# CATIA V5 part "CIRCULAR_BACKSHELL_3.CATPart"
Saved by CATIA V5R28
Part number: CIRCULAR_BACKSHELL_3
Revision: --A
Publications: "Logical Termination.1", "BCP", "BCPRPoint_generated(BCP)", "BCPPlane_generated(BCP)", "BaCP", "Face_generated(BaCP)", "Face_generated(BaCP).1", "MasterKeywayAxis", "Axis_generated(BaCP)"
Bounding box of the stored display mesh (mm): x 0 to 66.176, y -13.041 to 13.041, z -13.893 to 13.843
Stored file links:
  C:\Users\ajc8720\Documents\BOEING_WORK\0001-2CES\004-AP242\Boeing-Generic_Harness_R3\CIRCULAR_BACKSHELL_3.CATPart
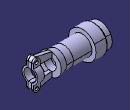
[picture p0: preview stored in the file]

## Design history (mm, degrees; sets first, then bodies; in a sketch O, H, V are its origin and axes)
Parameters
  PartNumber = "CIRCULAR_BACKSHELL_3"
AxisSystem1 "MasterKeywayAxis": origin (0, 0, 0), X (1, 0, 0), Y (0, 1, 0), Z (0, 0, 1)
Set1
  Point1: (34.417 {= Sketch2.distance(P3 V)}, 12.7, 0)
  Plane1: type 1Line1Pt, RefPoint Point1, Line Sketch2.L1
  Point2: type OnCurve, Support Sketch2.L4, Ratio 0.5
  Line1: type PtDir, RefPoint Point2, Direction (0, 1, 0), Start 0, End 5.08
  Point3: type OnCurve, Support Line1, Ratio 0.5
  Plane2: type 1Line1Pt, RefPoint Point3, Line Sketch2.L4
  Point4: type Center, Curve edge [face of Shaft1 from Sketch1.L5 | face of Shaft1 from Sketch1.L6]
  Plane3: type Tangent, Support face of Shaft1 from Sketch1.L5, RefPoint Point4
  Plane4: type OffsetPt, RefPlane Plane2, RefPoint Sketch2.P10
  Line2: type PtPt, FirstPoint vertex [face of Pad3 from Sketch5.L6 | face of Pad3 from Sketch5.L12 | end face of Pad3], SecondPoint vertex [face of Pad3 from Sketch5.L3 | face of Pad3 from Sketch5.L4 | start face of Pad3]
  Point5: type OnCurve, Support Line2, Ratio 0.5
  Plane5: type Tangent, Support face of Pad3 from Sketch5.L6, RefPoint Point5
Set2 "EGF"
  Set3 "BCP"
    Point6 "BCPRPoint": type Center, Curve edge [start face of Pad4 | face of Pad4 from Sketch6.A3]
    Plane6 "BCPPlane": type Tangent, Support start face of Pad4, RefPoint Point6
  Set4 "BaCP"
    Point7 "BaCPRPoint": type Center, Curve edge [face of Shaft1 from Sketch1.L6 | face of Shaft1 from Sketch1.L7]
    Plane7 "BaCPCPlane": type Tangent, Support face of Shaft1 from Sketch1.L7, RefPoint Point7
    Line3 "BaCPCLine": type PtDir, RefPoint Point7, Direction (0, 1, 0), Start 0, End 5.08
Body1 (main body)
  Sketch1 on xy-plane, origin (0, 0, 0), H (1, 0, 0), V (0, 1, 0)
    line L1 (0, 8.7249) -> (0, 11.43)
    line L2 (0, 11.43) -> (4.7625, 11.43)
    point P3 (4.7625, 11.43)
    line L3 (4.7625, 11.43) -> (6.3754, 13.0429)
    line L4 (6.3754, 13.0429) -> (16.764, 13.0429)
    line L5 (16.764, 13.0429) -> (16.764, 5.6896)
    line L6 (16.764, 5.6896) -> (7.747, 5.6896)
    line L7 (7.747, 5.6896) -> (7.747, 8.7249)
    line L8 (7.747, 8.7249) -> (0, 8.7249)
    axis line L9 (-2.2417, 0) -> (20.7737, 0)
    point P9 (-2.2417, 0)
    distance P3 L1 = 4.7625
    angle L3 L4 = 45
    distance L1 L7 = 7.747
    distance L1 L5 = 16.764
    distance L6 H = 5.6896
    distance L8 H = 8.7249
    distance L2 H = 11.43
    distance L4 H = 13.0429
    vertical: L1 V, L5 V, L7 V
    horizontal: L2 H, L4 H, L6 H, L8 H, L9 H
    coincidence: L1 V, P9 H
  Shaft1: profile Sketch1, axis Sketch1.L9, angle 360
  Sketch2 on zx-plane, origin (0, 0, 0), H (-1, 0, 0), V (0, 0, 1)
    line L1 (-34.417, 0) -> (-34.4298, 29.2976)
    line L2 (-34.417, 0) -> (-36.5055, 0)
    point P3 (-34.417, 0)
    line L3 (-34.417, 0) -> (-40.767, -0.0055)
    line L4 (-40.767, -0.0055) -> (-40.6296, -157.4316)
    reference projected point E1 (-34.417, 0) from Point1
    point P7 (-40.767, -0.0055)
    line L5 (-47.117, -0.0111) -> (-46.9796, -157.4371)
    construction line L6 (-40.767, -0.0055) -> (-47.117, -0.0111)
    construction line L7 (-40.6296, -157.4316) -> (-46.9796, -157.4371)
    point P10 (-47.117, -0.0111)
    point P11 (-34.417, 0)
    angle L1 V = 0.025
    distance P3 V = 34.417
    distance L4 E1 = 6.35
    angle L3 H = 0.05
    distance L4 L5 = 6.35
    horizontal: L2 H
    coincidence: L2 P3, L1 P3, L2 H, L4 P7, L3 P7, L3 P10, L5 P10, L1 P11, L3 P11
    perpendicularity: L4 L3, L6 L4, L6 L5, L7 L4, L7 L5
  Sketch3 on Plane3, origin (16.764, 0, 0), H (0, -1, 0), V (0, 0, 1)
    circle A1 centre (0, 0) radius 5.6896
    circle A2 centre (0, 0) radius 9.1186
    radius A1 = 5.6896
    radius A2 = 9.1186
  Pad1: profile Sketch3, direction (1, 0, 0), up to Plane1
  Sketch4 on Plane2, origin (40.616, 0, -173.0282), H (0, 1, 0), V (0.0009, 0, 1)
    circle A1 centre (0, 173.0227) radius 5.6896
    point P1 (0, 173.0227)
    circle A2 centre (0, 173.0227) radius 9.1186
    reference projected point E1 (0, 173.0227) from Sketch2.P7
    radius A1 = 5.6896
    radius A2 = 9.1186
    coincidence: P1 V, P1 E1
  Pad2: profile Sketch4, direction (-1, 0, 0.0009), up to Plane1
  Sketch5 on zx-plane, origin (0, 0, 0), H (-1, 0, 0), V (0, 0, 1)
    point P1 (0, 0)
    construction line L1 (0, 0) -> (-34.417, 0)
    point P2 (-34.417, 0)
    construction line L2 (-34.417, 0) -> (-47.117, -0.0111)
    point P3 (-47.117, -0.0111)
    point P4 (-47.0432, -84.6167)
    line L3 (-66.1763, 10.6657) -> (-66.1718, 5.5349)
    point P5 (-66.1718, 5.5349)
    line L4 (-66.1718, 5.5349) -> (-59.8218, 5.5404)
    line L5 (-47.122, 5.6785) -> (-47.1262, 10.4857)
    circle A1 centre (-63.0013, 10.6685) radius 1.8256
    arc A2 centre (-63.0013, 10.6685) radius 3.175 from (-66.1763, 10.6657) to (-62.3306, 13.7718) cw
    point P7 (-66.1763, 10.6657)
    point P8 (-62.3306, 13.7718)
    point P10 (-66.1621, -5.5903)
    point P12 (-66.1577, -10.7211)
    line L6 (-66.1577, -10.7211) -> (-66.1621, -5.5903)
    circle A3 centre (-62.9827, -10.7183) radius 1.8256
    line L7 (-62.3306, 13.7718) -> (-47.1262, 10.4857)
    point P13 (-62.3306, 13.7718)
    point P14 (-47.1262, 10.4857)
    point P15 (-62.3065, -13.8205)
    point P16 (-66.1577, -10.7211)
    arc A4 centre (-62.9827, -10.7183) radius 3.175 from (-66.1577, -10.7211) to (-62.3065, -13.8205) ccw
    point P18 (-47.1078, -10.5079)
    point P19 (-62.3065, -13.8205)
    line L8 (-62.3065, -13.8205) -> (-47.1078, -10.5079)
    construction line L9 (-40.775, 9.1131) -> (-156.7478, 34.1779)
    point P20 (-40.775, 9.1131)
    line L10 (-59.8218, 5.5404) -> (-59.822, 5.6674)
    line L11 (-59.822, 5.6674) -> (-47.122, 5.6785)
    point P22 (-59.8218, 5.5404)
    point P23 (-47.122, 5.6785)
    point P24 (-59.822, 5.6674)
    point P25 (-59.8121, -5.5848)
    point P26 (-66.1621, -5.5903)
    line L12 (-66.1621, -5.5903) -> (-59.8121, -5.5848)
    point P27 (-59.812, -5.7118)
    point P28 (-59.8121, -5.5848)
    line L13 (-59.8121, -5.5848) -> (-59.812, -5.7118)
    point P29 (-47.112, -5.7007)
    point P30 (-59.812, -5.7118)
    line L14 (-59.812, -5.7118) -> (-47.112, -5.7007)
    point P31 (-47.1078, -10.5079)
    point P32 (-47.112, -5.7007)
    line L15 (-47.112, -5.7007) -> (-47.1078, -10.5079)
    distance P1 P2 = 34.417
    angle L1 L2 = 0.05
    distance P3 P2 = 12.7
    distance L5 L3 = 19.05
    radius A1 = 1.8256
    radius A2 = 3.175
    distance L4 L2 = 5.5626
    distance A2 L2 = 13.8684
    distance P20 L2 = 9.1186
    distance P20 L5 = 6.35
    distance L10 L3 = 6.35
    distance L11 L2 = 5.6896
    horizontal: L1 H
    coincidence: P1 O, L5 P3, L7 P8, P8 A2, P4 L5, L7 L9
    tangency: A2 L3, A2 L7, L9 A2
    concentricity: A1 A2
    symmetry: P5 P10 L2, P7 P12 L2, L3 L6 L2, A1 A3 L2, P13 P15 L2, P7 P16 L2, A2 A4 L2, P14 P18 L2, P13 P19 L2, L7 L8 L2, P22 P25 L2, P5 P26 L2, L4 L12 L2, P24 P27 L2, P22 P28 L2, L10 L13 L2, P23 P29 L2, P24 P30 L2, L11 L14 L2, P14 P31 L2, P23 P32 L2, L5 L15 L2
    parallelism: L4 L2, L3 L5, L11 L4
    perpendicularity: L3 L2
  Pad3: profile Sketch5, direction (0, 1, 0), length 1.5875, opposite side length 1.5875
  Sketch6 on Plane5, origin (65.8993, 0, -306.7893), H (0, -1, 0), V (0.0009, 0, 1)
    arc A1 centre (0, 306.7617) radius 5.8097 from (1.6764, 312.3243) to (1.6764, 301.1991) cw
    point P1 (0, 306.7617)
    point P2 (1.6764, 312.3243)
    line L1 (1.6764, 312.3243) -> (1.6764, 320.6301)
    point P3 (1.6764, 320.6301)
    line L2 (1.6764, 292.8933) -> (1.6764, 301.1991)
    point P4 (1.6764, 292.8933)
    point P5 (1.6764, 301.1991)
    line L3 (3.2639, 292.8933) -> (3.2639, 300.1235)
    point P6 (3.2639, 292.8933)
    point P7 (3.2639, 300.1235)
    arc A2 centre (0, 306.7617) radius 7.3972 from (3.2639, 300.1235) to (3.2639, 313.3999) ccw
    point P8 (3.2639, 313.3999)
    line L4 (3.2639, 313.3999) -> (3.2639, 320.6301)
    point P9 (3.2639, 320.6301)
    line L5 (1.6764, 292.8933) -> (3.2639, 292.8933)
    line L6 (1.6764, 320.6301) -> (3.2639, 320.6301)
    construction line L7 (0, 306.7617) -> (0, 27.9514)
    point P11 (-1.6764, 312.3243)
    point P12 (-1.6764, 320.6301)
    point P13 (-1.6764, 292.8933)
    point P14 (-1.6764, 301.1991)
    point P15 (-3.2639, 292.8933)
    point P16 (-3.2639, 300.1235)
    point P17 (-3.2639, 313.3999)
    point P18 (-3.2639, 320.6301)
    point P19 (0, 306.7617)
    arc A3 centre (0, 306.7617) radius 5.8097 from (-1.6764, 312.3243) to (-1.6764, 301.1991) ccw
    line L8 (-1.6764, 312.3243) -> (-1.6764, 320.6301)
    line L9 (-1.6764, 292.8933) -> (-1.6764, 301.1991)
    line L10 (-3.2639, 292.8933) -> (-3.2639, 300.1235)
    arc A4 centre (0, 306.7617) radius 7.3972 from (-3.2639, 300.1235) to (-3.2639, 313.3999) cw
    line L11 (-3.2639, 313.3999) -> (-3.2639, 320.6301)
    line L12 (-1.6764, 292.8933) -> (-3.2639, 292.8933)
    line L13 (-1.6764, 320.6301) -> (-3.2639, 320.6301)
    reference projected point E1 (0, 306.7617) from Point5
    distance L2 L3 = 1.5875
    distance L2 P1 = 1.6764
    distance A1 A2 H = 1.5875
    distance L5 P1 = 13.8684
    distance L6 P1 = 13.8684
    distance P5 P19 V = 5.5626
    vertical: L1 V, L2 V, L7 V
    coincidence: P4 L1, L2 L1, L3 L4, P19 E1
    concentricity: A2 A1
    horizontal: L5 H, L6 H
    symmetry: P2 P11 L7, P3 P12 L7, P4 P13 L7, P5 P14 L7, P6 P15 L7, P7 P16 L7, P8 P17 L7, P9 P18 L7, A1 A3 L7, L1 L8 L7, L2 L9 L7, L3 L10 L7, A2 A4 L7, L4 L11 L7, L5 L12 L7, L6 L13 L7
  Pad4: profile Sketch6, direction (-1, 0, 0.0009), length 6.35
  Fillet1: radius 3.175 {= deleted_StrainReleaseWidth /2}, on edge [start face of Pad4 | face of Pad4 from Sketch6.L13]; edge [face of Pad4 from Sketch6.L13 | end face of Pad4]; edge [start face of Pad4 | face of Pad4 from Sketch6.L6]; edge [face of Pad4 from Sketch6.L6 | end face of Pad4]; edge [start face of Pad4 | face of Pad4 from Sketch6.L12]; edge [start face of Pad4 | face of Pad4 from Sketch6.L5]; edge [face of Pad4 from Sketch6.L12 | end face of Pad4]; edge [face of Pad4 from Sketch6.L5 | end face of Pad4]
  Sketch7 on face of Pad4 from Sketch6.L11, origin (72.7908, 3.2639, -31.7287), H (1, 0, 0), V (0, 0, -1)
    point P1 (-9.7895, -42.3972)
    reference projected arc E1 centre (-9.7895, -42.3972) radius 3.175 from (-7.5444, -44.6423) to (-7.5444, -40.1521) ccw from edge [face of Pad4 from Sketch6.L11 | face of Fillet1]
    concentricity: P1 E1
  Hole1: placed by Sketch7, at (63.0013, 3.2639, 10.6685) direction (0, -1, 0), diameter 3.175, up to face of Pad4 from Sketch6.L4
  Sketch8 on face of Pad4 from Sketch6.L10, origin (57.6407, 3.2639, -47.0401), H (1, 0, 0), V (0, 0, -1)
    point P1 (5.342, -36.3218)
    reference projected arc E1 centre (5.342, -36.3218) radius 3.175 from (7.5871, -34.0767) to (3.0969, -34.0767) ccw from edge [face of Pad4 from Sketch6.L10 | face of Fillet1]
    concentricity: P1 E1
  Hole2: placed by Sketch8, at (62.9827, 3.2639, -10.7183) direction (0, -1, 0), diameter 3.175, up to face of Pad4 from Sketch6.L3
  Sketch9 on zx-plane, origin (0, 0, 0), H (-1, 0, 0), V (0, 0, 1)
    construction line L1 (-24.3125, 0) -> (-34.417, 0)
    point P1 (-24.3125, 0)
    point P2 (-34.417, 0)
    construction line L2 (-34.417, 0) -> (-40.767, -0.0055)
    point P3 (-40.767, -0.0055)
    construction line L3 (-40.767, -0.0055) -> (-40.7059, -70.0577)
    line L4 (-47.1262, 10.4857) -> (-40.775, 9.1131)
    point P6 (-40.775, 9.1131)
    line L5 (-40.775, 9.1131) -> (-40.772, 5.6841)
    line L6 (-40.772, 5.6841) -> (-47.122, 5.6785)
    line L7 (-47.122, 5.6785) -> (-47.1262, 10.4857)
    axis line L8 (-40.767, -0.0055) -> (-163.6803, -0.1128)
    reference projected point E1 (-47.1262, 10.4857) from edge [face of Pad3 from Sketch5.L7 | face of Pad3 from Sketch5.L5]
    distance P2 V = 34.417
    angle L1 L2 = 0.05
    distance P2 P3 = 6.35
    distance P6 L2 = 9.1186 {= Sketch3.radius(A2)}
    distance L5 L7 = 6.35
    distance L6 L2 = 5.6896
    coincidence: P1 H, L5 L3, L4 E1
    horizontal: L1 H
    perpendicularity: L3 L2
    parallelism: L8 L2
  Shaft2: profile Sketch9, axis Sketch9.L8, angle 360
Body2 "BaCP"
  Sketch10 "Sketch" on Plane7, origin (7.747, 0, 0), H (0, 1, 0), V (0, 0, 1)
    line L1 (-0.672, 0.762) -> (0.672, 0.762)
    point P1 (-0.672, 0.762)
    point P2 (0.672, 0.762)
    arc A1 centre (0, 0) radius 1.016 from (-1.016, 0) to (1.016, 0) ccw
    point P3 (0, 0)
    point P4 (-1.016, 0)
    point P5 (1.016, 0)
    reference projected point E1 (0, 0) from Point7
    arc A2 centre (0, 0) radius 1.016 from (1.016, 0) to (0.672, 0.762) ccw
    point P6 (0, 0)
    point P7 (1.016, 0)
    point P8 (0.672, 0.762)
    arc A3 centre (0, 0) radius 1.016 from (-0.672, 0.762) to (-1.016, 0) ccw
    point P9 (0, 0)
    point P10 (-0.672, 0.762)
    point P11 (-1.016, 0)
    reference projected point E2 (0, 0) from Point7
    reference projected point E3 (0, 0) from Point7
    length L1 = 1.344
    radius A1 = 1.016
    radius A3 = 1.016
    radius A2 = 1.016
    distance L1 P5 = 0.762
    distance P4 L1 = 0.762
    distance P7 L1 = 0.762
    distance P11 L1 = 0.762
    coincidence: P3 E1, P6 E2, P9 E3, P8 P2, P10 P1
    horizontal: L1 H
  Pad5: profile Sketch10, direction (1, 0, 0), length 0.508, opposite side up to Plane7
